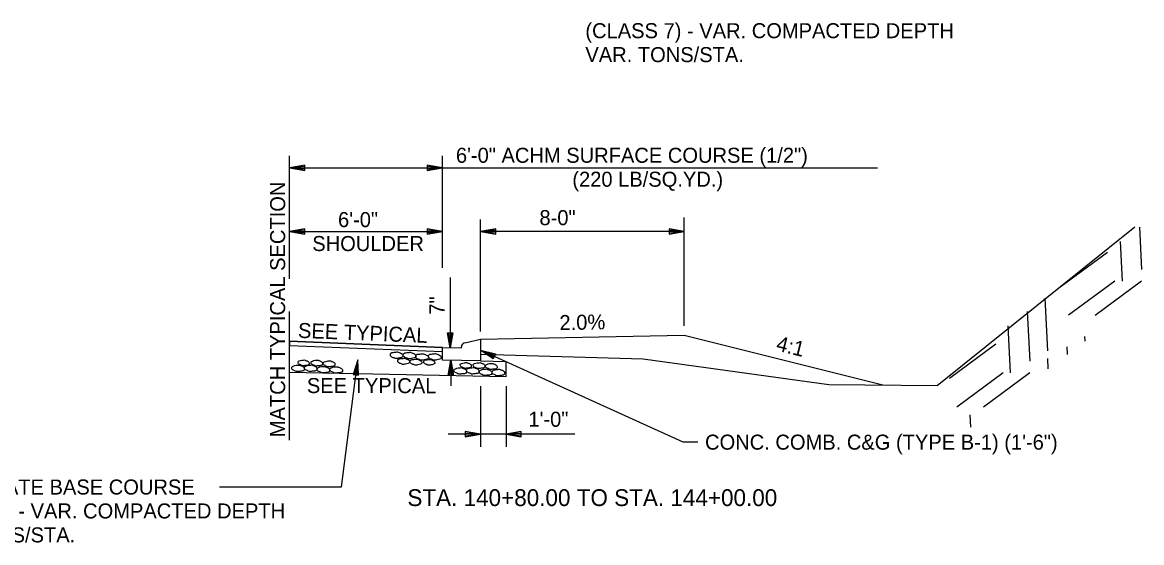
# Model space of a CAD drawing. Extents: x 1398183 to 1398373, y 1967240 to 1968889.
# Drawn here: x 1398257.9 to 1398301.84, y 1968531.11 to 1968551.54 of the extents above; entities that cross this region are included whole.
import ezdxf

# ---------------------------------------------------------------- set-up
doc = ezdxf.new("R2010")
doc.units = 0
for name, color, linetype in [('1', 7, 'Continuous'), ('10', 7, 'Continuous'), ('19', 7, 'Continuous'), ('42', 7, 'Continuous'), ('9', 7, 'Continuous'), ('Level 1', 7, 'Continuous')]:
    doc.layers.add(name, color=color, linetype=linetype)

# ---------------------------------------------------------------- blocks, each defined once
blk = doc.blocks.new('ROCKS')
at = {"layer": '1'}
blk.add_spline([(0.013, 0.06), (0.053, 0.053), (0.107, 0.033), (0.133, 0.013), (0.133, -0.007), (0.12, -0.033), (0.107, -0.04), (0.073, -0.053), (0.033, -0.067), (0.013, -0.067), (-0.02, -0.06), (-0.06, -0.053), (-0.087, -0.047), (-0.113, -0.02), (-0.113, -0.007), (-0.107, 0.02), (-0.087, 0.033), (-0.067, 0.047), (-0.033, 0.053), (-0.02, 0.06), (0.013, 0.06)], degree=3, dxfattribs=at)

msp = doc.modelspace()

# ---------------------------------------------------------------- linework, layer by layer
at = {"layer": '19'}
for p, q in [((1398268.387, 1968541.473), (1398268.387, 1968546.292)), ((1398268.987, 1968545.929), (1398268.387, 1968545.824)), ((1398268.987, 1968545.719), (1398268.987, 1968545.929)), ((1398273.787, 1968545.929), (1398273.787, 1968545.719)), ((1398274.387, 1968545.824), (1398273.787, 1968545.929)), ((1398274.387, 1968541.896), (1398274.387, 1968546.292)), ((1398268.387, 1968545.824), (1398291.472, 1968545.824)), ((1398268.387, 1968545.824), (1398268.987, 1968545.719)), ((1398268.987, 1968545.874), (1398268.547, 1968545.839)), ((1398268.547, 1968545.809), (1398268.987, 1968545.769)), ((1398274.227, 1968545.839), (1398273.787, 1968545.874)), ((1398273.787, 1968545.719), (1398274.387, 1968545.824)), ((1398273.787, 1968545.769), (1398274.227, 1968545.809)), ((1398275.887, 1968539.396), (1398275.887, 1968543.794)), ((1398283.887, 1968539.629), (1398283.887, 1968543.871)), ((1398268.987, 1968543.429), (1398268.387, 1968543.324)), ((1398268.387, 1968543.324), (1398274.387, 1968543.324)), ((1398268.387, 1968543.324), (1398268.987, 1968543.219)), ((1398268.987, 1968543.374), (1398268.547, 1968543.339)), ((1398268.547, 1968543.309), (1398268.987, 1968543.269)), ((1398268.987, 1968543.219), (1398268.987, 1968543.429)), ((1398273.787, 1968543.429), (1398273.787, 1968543.219)), ((1398274.387, 1968543.324), (1398273.787, 1968543.429)), ((1398274.227, 1968543.339), (1398273.787, 1968543.374)), ((1398273.787, 1968543.219), (1398274.387, 1968543.324)), ((1398273.787, 1968543.269), (1398274.227, 1968543.309)), ((1398276.487, 1968543.429), (1398275.887, 1968543.324)), ((1398283.887, 1968543.324), (1398275.887, 1968543.324)), ((1398275.887, 1968543.324), (1398276.487, 1968543.219)), ((1398276.487, 1968543.374), (1398276.047, 1968543.339)), ((1398276.047, 1968543.309), (1398276.487, 1968543.269)), ((1398276.487, 1968543.219), (1398276.487, 1968543.429)), ((1398283.287, 1968543.429), (1398283.287, 1968543.219)), ((1398283.887, 1968543.324), (1398283.287, 1968543.429)), ((1398283.727, 1968543.339), (1398283.287, 1968543.374)), ((1398283.287, 1968543.219), (1398283.887, 1968543.324)), ((1398283.287, 1968543.269), (1398283.727, 1968543.309)), ((1398274.692, 1968541.518), (1398274.692, 1968538.753)), ((1398268.387, 1968535.135), (1398268.387, 1968540.187)), ((1398274.587, 1968539.353), (1398274.797, 1968539.353)), ((1398274.692, 1968538.753), (1398274.587, 1968539.353)), ((1398274.677, 1968538.913), (1398274.637, 1968539.353)), ((1398274.797, 1968539.353), (1398274.692, 1968538.753)), ((1398274.742, 1968539.353), (1398274.707, 1968538.913)), ((1398275.267, 1968538.957), (1398275.887, 1968539.095)), ((1398275.887, 1968539.095), (1398283.887, 1968539.255)), ((1398275.887, 1968539.095), (1398275.887, 1968538.246)), ((1398283.887, 1968539.255), (1398291.686, 1968537.305)), ((1398274.387, 1968538.276), (1398274.387, 1968538.776)), ((1398274.387, 1968538.776), (1398275.137, 1968538.761)), ((1398275.137, 1968538.761), (1398275.137, 1968538.794)), ((1398283.847, 1968535.055), (1398275.887, 1968538.671)), ((1398276.388, 1968538.328), (1398275.887, 1968538.671)), ((1398275.887, 1968538.671), (1398276.476, 1968538.517)), ((1398276.408, 1968538.373), (1398276.025, 1968538.59)), ((1398276.036, 1968538.616), (1398276.451, 1968538.47)), ((1398276.476, 1968538.517), (1398276.388, 1968538.328)), ((1398270.432, 1968533.302), (1398271.069, 1968538.288)), ((1398271.069, 1968538.288), (1398270.89, 1968537.706)), ((1398271.037, 1968538.132), (1398270.943, 1968537.702)), ((1398271.048, 1968537.688), (1398271.065, 1968538.128)), ((1398271.097, 1968537.681), (1398271.069, 1968538.288)), ((1398275.887, 1968538.246), (1398274.387, 1968538.276)), ((1398274.615, 1968537.67), (1398274.72, 1968538.27)), ((1398274.665, 1968537.67), (1398274.705, 1968538.11)), ((1398274.72, 1968538.27), (1398274.825, 1968537.67)), ((1398274.72, 1968538.27), (1398274.72, 1968537.27)), ((1398274.735, 1968538.11), (1398274.77, 1968537.67)), ((1398276.887, 1968537.638), (1398276.887, 1968538.226)), ((1398270.89, 1968537.706), (1398271.097, 1968537.681)), ((1398274.825, 1968537.67), (1398274.615, 1968537.67)), ((1398275.887, 1968537.256), (1398275.887, 1968534.872)), ((1398276.887, 1968537.256), (1398276.887, 1968534.872)), ((1398279.592, 1968535.364), (1398274.611, 1968535.364)), ((1398275.287, 1968535.469), (1398275.287, 1968535.259)), ((1398275.887, 1968535.364), (1398275.287, 1968535.469)), ((1398275.727, 1968535.379), (1398275.287, 1968535.414)), ((1398275.287, 1968535.259), (1398275.887, 1968535.364)), ((1398277.487, 1968535.469), (1398276.887, 1968535.364)), ((1398276.887, 1968535.364), (1398277.487, 1968535.259)), ((1398277.487, 1968535.414), (1398277.047, 1968535.379)), ((1398277.487, 1968535.259), (1398277.487, 1968535.469)), ((1398275.287, 1968535.309), (1398275.727, 1968535.349)), ((1398277.047, 1968535.349), (1398277.487, 1968535.309)), ((1398284.417, 1968535.055), (1398283.847, 1968535.055)), ((1398265.634, 1968533.302), (1398270.432, 1968533.302))]:
    msp.add_line(p, q, dxfattribs=at)
for points in [[(1398268.387, 1968539.016), (1398274.387, 1968538.776)], [(1398275.887, 1968538.246), (1398276.887, 1968538.226)], [(1398268.387, 1968537.808), (1398276.887, 1968537.638)]]:
    msp.add_lwpolyline(points, dxfattribs=at)
msp.add_lwpolyline([(1398268.387, 1968538.85), (1398274.387, 1968538.61), (1398274.387, 1968538.776), (1398268.387, 1968539.016)], close=True, dxfattribs=at)
msp.add_arc((1398275.303, 1968538.794), 0.167, 102.5288, 180, dxfattribs=at)
at = {"layer": '42'}
msp.add_lwpolyline([(1398275.887, 1968538.509), (1398282.274, 1968538.326), (1398289.56, 1968537.325), (1398293.811, 1968537.285), (1398301.576, 1968543.51)], dxfattribs=at)
at = {"layer": '9'}
for p, q in [((1398301.756, 1968543.503), (1398301.841, 1968541.841)), ((1398300.995, 1968542.931), (1398301.075, 1968541.38)), ((1398300.505, 1968542.507), (1398298.687, 1968541.162)), ((1398300.796, 1968541.38), (1398298.978, 1968540.035)), ((1398301.842, 1968541.377), (1398300.024, 1968540.032)), ((1398298.039, 1968540.708), (1398298.145, 1968538.643)), ((1398297.352, 1968540.191), (1398297.453, 1968538.238)), ((1398296.591, 1968539.618), (1398296.686, 1968537.777)), ((1398296.117, 1968538.904), (1398294.298, 1968537.559)), ((1398299.602, 1968539.205), (1398299.612, 1968539.019)), ((1398298.909, 1968538.799), (1398298.924, 1968538.502)), ((1398298.142, 1968538.339), (1398298.163, 1968537.93)), ((1398296.408, 1968537.777), (1398294.589, 1968536.432)), ((1398297.453, 1968537.774), (1398295.635, 1968536.429)), ((1398295.101, 1968536.121), (1398295.126, 1968535.645))]:
    msp.add_line(p, q, dxfattribs=at)

# ---------------------------------------------------------------- block references
at = {"layer": 'Level 1'}
for p, xscale, yscale, rotation in [((1398272.571, 1968538.464), 2.0116542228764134, -2.011654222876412, -4.336484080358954), ((1398273.076, 1968538.452), 2.0116542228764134, -2.011654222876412, -4.336484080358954), ((1398273.57, 1968538.397), 2.0116542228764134, -2.011654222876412, -4.336484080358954), ((1398274.068, 1968538.4), 2.0116542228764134, -2.011654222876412, -4.336484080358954), ((1398268.743, 1968537.957), 2.0116542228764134, -2.011654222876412, 175.66351591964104), ((1398268.957, 1968538.171), 1.773922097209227, -1.7739220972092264, 175.66351591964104), ((1398269.241, 1968537.961), 2.0116542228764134, -2.011654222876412, 175.66351591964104), ((1398269.479, 1968538.164), 1.851115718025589, -1.8511157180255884, 175.66351591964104), ((1398269.735, 1968537.905), 2.0116542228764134, -2.011654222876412, 175.66351591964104), ((1398269.961, 1968538.133), 1.8866375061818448, -1.886637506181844, 175.66351591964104), ((1398270.24, 1968537.894), 2.0116542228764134, -2.011654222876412, 175.66351591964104), ((1398272.85, 1968538.225), 1.8866375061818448, -1.886637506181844, -4.336484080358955), ((1398273.332, 1968538.194), 1.851115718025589, -1.8511157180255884, -4.336484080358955), ((1398273.853, 1968538.187), 1.773922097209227, -1.7739220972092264, -4.336484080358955), ((1398275.111, 1968537.856), 2.0116542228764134, -2.011654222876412, 175.66351591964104), ((1398275.325, 1968538.07), 1.773922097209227, -1.7739220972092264, 175.66351591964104), ((1398275.608, 1968537.86), 2.0116542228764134, -2.011654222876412, 175.66351591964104), ((1398275.846, 1968538.063), 1.851115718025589, -1.8511157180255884, 175.66351591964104), ((1398276.329, 1968538.032), 1.8866375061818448, -1.886637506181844, 175.66351591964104), ((1398276.103, 1968537.804), 2.0116542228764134, -2.011654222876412, 175.66351591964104), ((1398276.608, 1968537.793), 2.0116542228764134, -2.011654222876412, 175.66351591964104)]:
    msp.add_blockref('ROCKS', p, dxfattribs=dict(at, xscale=xscale, yscale=yscale, rotation=rotation))

# ---------------------------------------------------------------- texts
at = {"layer": '10'}
for s, height, p in [('6\'-0" ACHM SURFACE COURSE (1/2")', 0.59001, (1398274.92, 1968546.025)), ('(220 LB/SQ.YD.)', 0.59001, (1398279.491, 1968545.085)), ('8-0"', 0.59, (1398278.2, 1968543.576)), ('6\'-0"', 0.59, (1398270.292, 1968543.499)), ('SHOULDER', 0.59, (1398269.28, 1968542.559)), ('1\'-0"', 0.59, (1398277.766, 1968535.659))]:
    msp.add_text(s, height=height, dxfattribs=at).set_placement(p)
for s, height, rotation, p in [('MATCH TYPICAL SECTION', 0.59001, 90, (1398268.215, 1968535.248)), ('2.0%', 0.59, 1.1458, (1398278.991, 1968539.452)), ('SEE TYPICAL', 0.59001, 357.7094, (1398268.711, 1968539.153)), ('4:1', 0.59, 345.9638, (1398287.461, 1968538.665)), ('SEE TYPICAL', 0.59001, 359.948, (1398269.068, 1968536.982))]:
    msp.add_text(s, height=height, rotation=rotation, dxfattribs=at).set_placement(p)
at = {"layer": '19'}
for s, p in [('(CLASS 7) - VAR. COMPACTED DEPTH', (1398280.003, 1968550.918)), ('VAR. TONS/STA.', (1398280.003, 1968549.978)), ('AGGREGATE BASE COURSE', (1398253.749, 1968532.998)), ('(CLASS 7) - VAR. COMPACTED DEPTH', (1398253.749, 1968532.058)), ('VAR. TONS/STA.', (1398253.749, 1968531.118))]:
    msp.add_text(s, height=0.59001, rotation=360, dxfattribs=at).set_placement(p)
for s, height, p in [('CONC. COMB. C&G (TYPE B-1) (1\'-6")', 0.59001, (1398284.702, 1968534.76)), ('STA. 140+80.00 TO STA. 144+00.00', 0.65999, (1398273.014, 1968532.545))]:
    msp.add_text(s, height=height, dxfattribs=at).set_placement(p)
at = {"layer": '42'}
msp.add_text('7"', height=0.59, rotation=90, dxfattribs=at).set_placement((1398274.472, 1968540.061))

doc.saveas('drawing.dxf')
